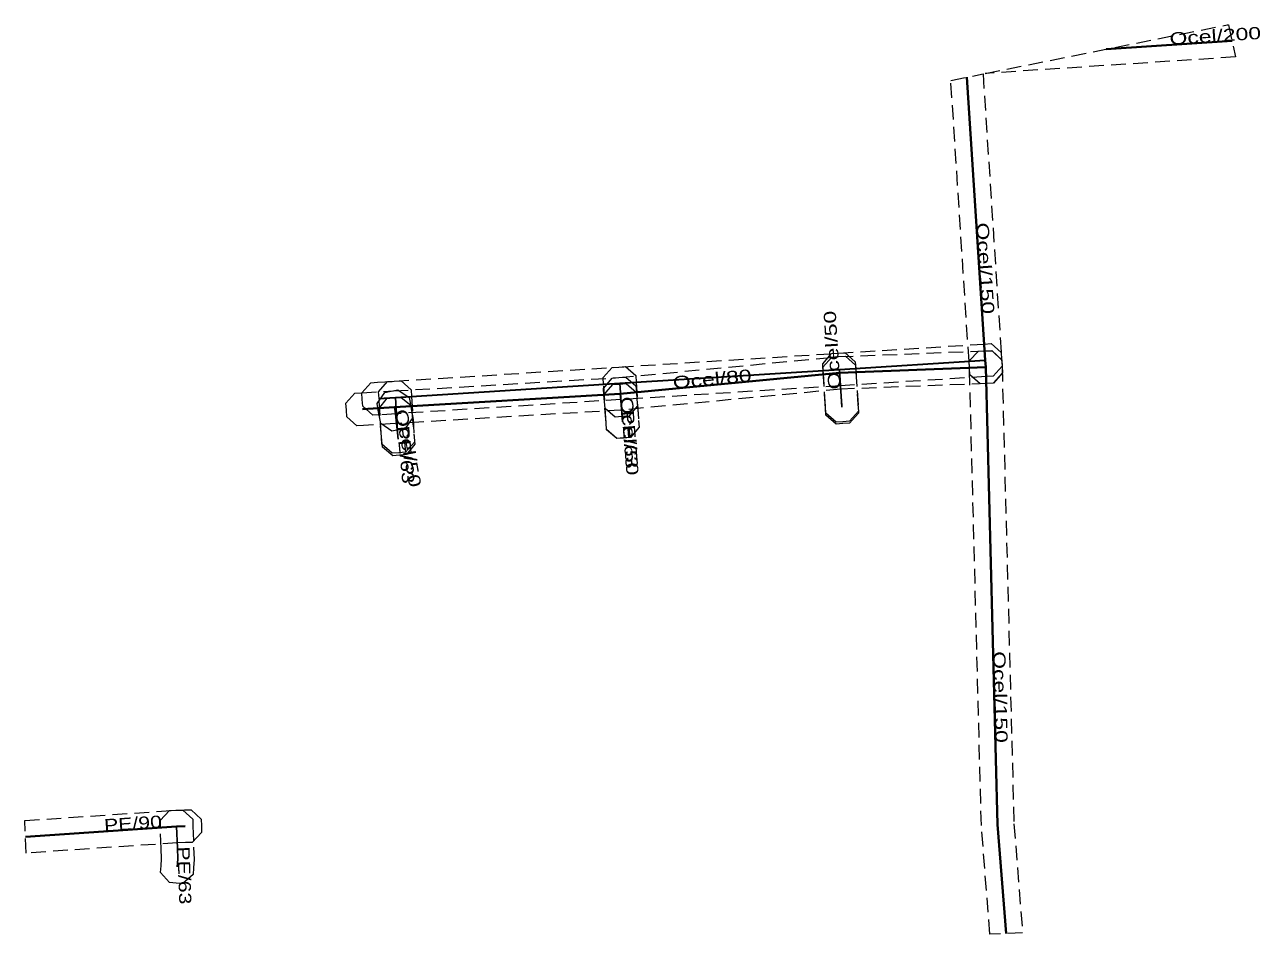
# Model space of a CAD drawing. Extents: x -474168.9 to -474093.1, y -1105851.4 to -1105795.7.
import ezdxf

# ---------------------------------------------------------------- set-up
doc = ezdxf.new("R2010")
doc.units = 0
doc.header["$LTSCALE"] = 0.3
doc.linetypes.add('MEDIUM_DASHED', pattern=[4.5, 3, -1.5])
for name, color, linetype, lineweight in [('1', 7, 'MEDIUM_DASHED', 13), ('14', 7, 'Continuous', 25), ('15', 7, 'Continuous', 25), ('51', 7, 'MEDIUM_DASHED', 13)]:
    doc.layers.add(name, color=color, linetype=linetype, lineweight=lineweight)
doc.layers.add('20', color=7, linetype='Continuous')

msp = doc.modelspace()

# ---------------------------------------------------------------- linework, layer by layer
at = {"layer": '1'}
for points in [[(-474094.594, -1105797.633), (-474109.945, -1105798.644), (-474095.11, -1105795.663), (-474095.028, -1105795.658)], [(-474110.944, -1105816.298), (-474112.064, -1105799.07), (-474110.085, -1105798.672), (-474108.948, -1105816.17), (-474108.921, -1105816.592), (-474108.894, -1105817.005), (-474109.442, -1105817.627), (-474109.855, -1105817.654), (-474110.268, -1105817.681), (-474110.89, -1105817.133), (-474110.917, -1105816.72)], [(-474109.466, -1105817.639), (-474109.88, -1105817.655), (-474118.815, -1105818.006), (-474132.264, -1105819.287), (-474146.138, -1105820.109), (-474148.082, -1105820.224), (-474148.495, -1105820.248), (-474149.115, -1105819.698), (-474149.139, -1105819.285), (-474149.163, -1105818.872), (-474148.613, -1105818.252), (-474148.2, -1105818.228), (-474146.256, -1105818.113), (-474132.418, -1105817.293), (-474118.949, -1105816.01), (-474109.958, -1105815.657), (-474109.544, -1105815.641), (-474108.936, -1105816.203), (-474108.92, -1105816.617), (-474108.904, -1105817.031)], [(-474107.662, -1105851.346), (-474109.662, -1105851.428), (-474110.188, -1105844.755), (-474110.919, -1105816.682), (-474110.93, -1105816.268), (-474110.359, -1105815.667), (-474109.945, -1105815.656), (-474109.531, -1105815.645), (-474108.93, -1105816.216), (-474108.919, -1105816.63), (-474108.19, -1105844.651)], [(-474119.726, -1105819.48), (-474119.753, -1105819.067), (-474119.88, -1105817.071), (-474119.906, -1105816.658), (-474119.358, -1105816.037), (-474118.945, -1105816.01), (-474118.532, -1105815.984), (-474117.911, -1105816.532), (-474117.884, -1105816.945), (-474117.757, -1105818.941), (-474117.731, -1105819.354), (-474118.279, -1105819.975), (-474118.692, -1105820.002), (-474119.105, -1105820.028)], [(-474131.376, -1105817.8), (-474131.344, -1105818.213), (-474131.313, -1105818.613), (-474131.281, -1105819.026), (-474131.82, -1105819.655), (-474132.233, -1105819.687), (-474132.646, -1105819.719), (-474133.275, -1105819.18), (-474133.307, -1105818.767), (-474133.338, -1105818.367), (-474133.37, -1105817.954), (-474132.831, -1105817.325), (-474132.418, -1105817.293), (-474132.005, -1105817.261)], [(-474145.291, -1105818.519), (-474145.214, -1105818.926), (-474145.137, -1105819.335), (-474145.06, -1105819.742), (-474145.528, -1105820.426), (-474145.935, -1105820.503), (-474146.342, -1105820.58), (-474147.026, -1105820.112), (-474147.103, -1105819.705), (-474147.18, -1105819.296), (-474147.257, -1105818.889), (-474146.789, -1105818.205), (-474146.382, -1105818.128), (-474145.975, -1105818.051)], [(-474131.344, -1105818.201), (-474131.313, -1105818.614), (-474131.213, -1105819.924), (-474131.182, -1105820.337), (-474131.721, -1105820.966), (-474132.134, -1105820.997), (-474132.547, -1105821.028), (-474133.176, -1105820.489), (-474133.207, -1105820.076), (-474133.307, -1105818.766), (-474133.338, -1105818.353), (-474132.799, -1105817.724), (-474132.386, -1105817.693), (-474131.973, -1105817.662)], [(-474145.165, -1105819.011), (-474145.125, -1105819.423), (-474144.975, -1105820.963), (-474144.935, -1105821.375), (-474145.461, -1105822.015), (-474145.873, -1105822.055), (-474146.285, -1105822.095), (-474146.925, -1105821.569), (-474146.965, -1105821.157), (-474147.115, -1105819.617), (-474147.155, -1105819.205), (-474146.629, -1105818.565), (-474146.217, -1105818.525), (-474145.805, -1105818.485)], [(-474159.501, -1105845.822), (-474168.772, -1105846.45), (-474168.871, -1105844.452), (-474159.599, -1105843.824), (-474159.065, -1105843.807), (-474158.651, -1105843.794), (-474158.047, -1105844.362), (-474158.034, -1105844.776), (-474158.021, -1105845.19), (-474158.589, -1105845.794), (-474159.003, -1105845.807)], [(-474158.565, -1105844.375), (-474158.551, -1105844.789), (-474158.507, -1105846.091), (-474158.481, -1105846.839), (-474158.514, -1105847.353), (-474158.541, -1105847.766), (-474159.164, -1105848.313), (-474159.577, -1105848.286), (-474159.99, -1105848.259), (-474160.537, -1105847.636), (-474160.51, -1105847.223), (-474160.483, -1105846.809), (-474160.505, -1105846.159), (-474160.549, -1105844.857), (-474160.563, -1105844.443), (-474159.998, -1105843.838), (-474159.584, -1105843.824), (-474159.17, -1105843.81)]]:
    msp.add_lwpolyline(points, close=True, dxfattribs=at)
at = {"layer": '14', "lineweight": 40}
msp.add_line((-474102.526, -1105797.153), (-474094.811, -1105796.645), dxfattribs=at)
at = {"layer": '14'}
for p, q in [((-474118.755, -1105819.004), (-474118.882, -1105817.008)), ((-474132.341, -1105818.29), (-474132.31, -1105818.69)), ((-474132.31, -1105818.69), (-474132.21, -1105820)), ((-474146.197, -1105819.111), (-474146.12, -1105819.52)), ((-474146.12, -1105819.52), (-474145.97, -1105821.06))]:
    msp.add_line(p, q, dxfattribs=at)
at = {"layer": '14', "lineweight": 40}
for points in [[(-474111.074, -1105798.871), (-474109.946, -1105816.234), (-474109.919, -1105816.656)], [(-474109.919, -1105816.656), (-474118.882, -1105817.008), (-474132.341, -1105818.29), (-474146.197, -1105819.111), (-474148.141, -1105819.226)], [(-474109.919, -1105816.656), (-474109.189, -1105844.703), (-474108.662, -1105851.387)], [(-474159.034, -1105844.807), (-474159.55, -1105844.823), (-474168.821, -1105845.451)]]:
    msp.add_lwpolyline(points, dxfattribs=at)
at = {"layer": '14'}
msp.add_lwpolyline([(-474159.55, -1105844.823), (-474159.506, -1105846.125), (-474159.482, -1105846.824), (-474159.512, -1105847.288)], dxfattribs=at)
at = {"layer": '15'}
for p, q in [((-474118.895, -1105816.798), (-474118.748, -1105819.117)), ((-474132.36, -1105817.646), (-474132.21, -1105820.002)), ((-474146.136, -1105818.514), (-474145.984, -1105820.904))]:
    msp.add_line(p, q, dxfattribs=at)
at = {"layer": '15', "lineweight": 35}
msp.add_lwpolyline([(-474147.165, -1105818.579), (-474146.136, -1105818.514), (-474132.36, -1105817.646), (-474118.895, -1105816.798), (-474109.946, -1105816.234)], dxfattribs=at)
at = {"layer": '51'}
for points in [[(-474147.641, -1105817.607), (-474147.228, -1105817.581), (-474146.199, -1105817.516), (-474132.423, -1105816.648), (-474118.958, -1105815.8), (-474110.009, -1105815.236), (-474109.596, -1105815.21), (-474108.974, -1105815.758), (-474108.948, -1105816.171), (-474108.922, -1105816.584), (-474109.47, -1105817.206), (-474109.883, -1105817.232), (-474118.832, -1105817.796), (-474132.297, -1105818.644), (-474146.073, -1105819.512), (-474147.102, -1105819.577), (-474147.515, -1105819.603), (-474148.137, -1105819.055), (-474148.163, -1105818.642), (-474148.189, -1105818.229)], [(-474117.923, -1105816.322), (-474117.897, -1105816.735), (-474117.75, -1105819.054), (-474117.724, -1105819.467), (-474118.272, -1105820.089), (-474118.685, -1105820.115), (-474119.098, -1105820.141), (-474119.72, -1105819.593), (-474119.746, -1105819.18), (-474119.893, -1105816.861), (-474119.919, -1105816.448), (-474119.371, -1105815.826), (-474118.958, -1105815.8), (-474118.545, -1105815.774)], [(-474131.389, -1105817.169), (-474131.362, -1105817.582), (-474131.212, -1105819.938), (-474131.185, -1105820.351), (-474131.733, -1105820.973), (-474132.146, -1105821), (-474132.559, -1105821.027), (-474133.181, -1105820.479), (-474133.208, -1105820.066), (-474133.358, -1105817.71), (-474133.385, -1105817.297), (-474132.837, -1105816.675), (-474132.424, -1105816.648), (-474132.011, -1105816.621)], [(-474145.164, -1105818.038), (-474145.138, -1105818.451), (-474144.986, -1105820.841), (-474144.96, -1105821.254), (-474145.508, -1105821.876), (-474145.921, -1105821.902), (-474146.334, -1105821.928), (-474146.956, -1105821.38), (-474146.982, -1105820.967), (-474147.134, -1105818.577), (-474147.16, -1105818.164), (-474146.612, -1105817.542), (-474146.199, -1105817.516), (-474145.786, -1105817.49)]]:
    msp.add_lwpolyline(points, close=True, dxfattribs=at)

# ---------------------------------------------------------------- texts
at = {"layer": '20'}
for s, rotation, width, p in [('Ocel/200', 3.767, 1.4, (-474098.619, -1105796.896)), ('Ocel/150', 273.718, 1.4, (-474110.493, -1105807.813)), ('Ocel/50', 93.641, 1.4, (-474118.819, -1105818.006)), ('Ocel/80', 5.441, 1.4, (-474129.075, -1105817.979)), ('Ocel/50', 274.432, 1.4, (-474132.325, -1105818.49)), ('Ocel/50', 280.662, 1.4, (-474146.158, -1105819.315)), ('PE/63', 274.365, 1.3, (-474132.26, -1105819.345)), ('PE/63', 275.563, 1.3, (-474146.045, -1105820.29)), ('Ocel/150', 271.491, 1.4, (-474109.465, -1105834.081)), ('PE/90', 3.878, 1.3, (-474163.978, -1105845.123)), ('PE/63', 271.936, 1.3, (-474159.508, -1105846.056))]:
    msp.add_text(s, height=0.75, rotation=rotation, dxfattribs=dict(at, width=width)).set_placement(p)

doc.saveas('drawing.dxf')
